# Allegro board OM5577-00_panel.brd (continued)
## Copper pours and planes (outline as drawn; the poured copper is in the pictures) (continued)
(no net) on TOP, IS1, IS2: 286,5.5 272.7,5.5 272.7,8.65 271.85,9.5 246.55,9.5 245.7,8.65 245.7,0.5 232.5,0.5 232.5,68.5 232.51,68.5 234.25,68.5 234.25,29.45 284.25,29.45 284.25,68.5 285.99,68.5 286,68.5
(no net) on TOP, IS1, IS2: 54,5.5 40.7,5.5 40.7,8.65 39.85,9.5 14.55,9.5 13.7,8.65 13.7,0.5 0.5,0.5 0.5,68.5 0.51,68.5 2.25,68.5 2.25,29.45 52.25,29.45 52.25,68.5 53.99,68.5 54,68.5
(no net) on TOP, IS1, IS2: 228,5.5 214.7,5.5 214.7,8.65 213.85,9.5 188.55,9.5 187.7,8.65 187.7,0.5 174.5,0.5 174.5,68.5 174.51,68.5 176.25,68.5 176.25,29.45 226.25,29.45 226.25,68.5 227.99,68.5 228,68.5
(no net) on TOP, IS1, IS2: 170,5.5 156.7,5.5 156.7,8.65 155.85,9.5 130.55,9.5 129.7,8.65 129.7,0.5 116.5,0.5 116.5,68.5 116.51,68.5 118.25,68.5 118.25,29.45 168.25,29.45 168.25,68.5 169.99,68.5 170,68.5
(no net) on BOTTOM: 187.5,169.5 147.5,169.5 147.5,193 166.7,193 166.7,194.25 167.15,194.7 167.75,194.7 168.2,194.25 168.2,193 187.5,193 ; 3 cut-outs
(no net) on BOTTOM: 104.75,22.38 101.67,19.3 101.69,19.26 101.77,18.96 101.78,18.66 101.86,18.51 102.03,18.54 105.15,21.66 105.15,29.16 105.44,29.45 105.95,29.45 105.95,29.96 106.49,30.5 107.12,30.5 107.18,30.54 107.18,30.62 107.15,30.66 107.13,30.7 106.21,30.7 110.25,34.74 110.25,68.5 111.99,68.5 112,68.5 112,5.5 98.7,5.5 98.7,8.65 97.85,9.5 72.55,9.5 71.7,8.65 71.7,0.5 58.5,0.5 58.5,68.5 58.51,68.5 60.25,68.5 60.25,29.45 104.96,29.45 104.75,29.24
(no net) on BOTTOM: 234.75,169.5 194.75,169.5 194.75,193 213.95,193 213.95,194.25 214.4,194.7 215,194.7 215.45,194.25 215.45,193 234.75,193 ; 3 cut-outs
(no net) on BOTTOM: 113.5,80.05 110.94,77.5 61.01,77.5 58.5,80 58.5,159 61,161.5 110.95,161.5 113.5,158.95 ; 7 cut-outs
(no net) on BOTTOM: 45.75,169.5 5.75,169.5 5.75,193 24.95,193 24.95,194.25 25.4,194.7 26,194.7 26.45,194.25 26.45,193 45.75,193 ; 3 cut-outs
(no net) on BOTTOM: 140.25,169.5 100.25,169.5 100.25,193 119.45,193 119.45,194.25 119.9,194.7 120.5,194.7 120.95,194.25 120.95,193 140.25,193 ; 3 cut-outs
(no net) on BOTTOM: 93,169.5 53,169.5 53,193 72.2,193 72.2,194.25 72.65,194.7 73.25,194.7 73.7,194.25 73.7,193 93,193 ; 3 cut-outs
(no net) on BOTTOM: 278.75,22.38 275.67,19.3 275.69,19.26 275.77,18.96 275.78,18.66 275.86,18.51 276.03,18.54 279.15,21.66 279.15,29.16 279.44,29.45 279.95,29.45 279.95,29.96 280.49,30.5 281.12,30.5 281.18,30.54 281.18,30.62 281.15,30.66 281.13,30.7 280.21,30.7 284.25,34.74 284.25,68.5 285.99,68.5 286,68.5 286,5.5 272.7,5.5 272.7,8.65 271.85,9.5 246.55,9.5 245.7,8.65 245.7,0.5 232.5,0.5 232.5,68.5 232.51,68.5 234.25,68.5 234.25,29.45 278.96,29.45 278.75,29.24
(no net) on BOTTOM: 220.75,22.38 217.67,19.3 217.69,19.26 217.77,18.96 217.78,18.66 217.86,18.51 218.03,18.54 221.15,21.66 221.15,29.16 221.44,29.45 221.95,29.45 221.95,29.96 222.49,30.5 223.12,30.5 223.18,30.54 223.18,30.62 223.15,30.66 223.13,30.7 222.21,30.7 226.25,34.74 226.25,68.5 227.99,68.5 228,68.5 228,5.5 214.7,5.5 214.7,8.65 213.85,9.5 188.55,9.5 187.7,8.65 187.7,0.5 174.5,0.5 174.5,68.5 174.51,68.5 176.25,68.5 176.25,29.45 220.96,29.45 220.75,29.24
(no net) on BOTTOM: 55.5,80.05 52.94,77.5 3.01,77.5 0.5,80 0.5,159 3,161.5 52.95,161.5 55.5,158.95 ; 7 cut-outs
(no net) on BOTTOM: 171.5,80.05 168.94,77.5 119.01,77.5 116.5,80 116.5,159 119,161.5 168.95,161.5 171.5,158.95 ; 7 cut-outs
(no net) on BOTTOM: 162.75,22.38 159.67,19.3 159.69,19.26 159.77,18.96 159.78,18.66 159.86,18.51 160.03,18.54 163.15,21.66 163.15,29.16 163.44,29.45 163.95,29.45 163.95,29.96 164.49,30.5 165.12,30.5 165.18,30.54 165.18,30.62 165.15,30.66 165.13,30.7 164.21,30.7 168.25,34.74 168.25,68.5 169.99,68.5 170,68.5 170,5.5 156.7,5.5 156.7,8.65 155.85,9.5 130.55,9.5 129.7,8.65 129.7,0.5 116.5,0.5 116.5,68.5 116.51,68.5 118.25,68.5 118.25,29.45 162.96,29.45 162.75,29.24
(no net) on BOTTOM: 46.75,22.38 43.67,19.3 43.69,19.26 43.77,18.96 43.78,18.66 43.86,18.51 44.03,18.54 47.15,21.66 47.15,29.16 47.44,29.45 47.95,29.45 47.95,29.96 48.49,30.5 49.12,30.5 49.18,30.54 49.18,30.62 49.15,30.66 49.13,30.7 48.21,30.7 52.25,34.74 52.25,68.5 53.99,68.5 54,68.5 54,5.5 40.7,5.5 40.7,8.65 39.85,9.5 14.55,9.5 13.7,8.65 13.7,0.5 0.5,0.5 0.5,68.5 0.51,68.5 2.25,68.5 2.25,29.45 46.96,29.45 46.75,29.24
(no net) on BOTTOM: 282,169.5 242,169.5 242,193 261.2,193 261.2,194.25 261.65,194.7 262.25,194.7 262.7,194.25 262.7,193 282,193 ; 3 cut-outs
(no net) on BOTTOM: 229.5,80.05 226.94,77.5 177.01,77.5 174.5,80 174.5,159 177,161.5 226.95,161.5 229.5,158.95 ; 7 cut-outs
(no net) on BOTTOM: 287.5,80.05 284.94,77.5 235.01,77.5 232.5,80 232.5,159 235,161.5 284.95,161.5 287.5,158.95 ; 7 cut-outs
(no net) on IS1, IS2: 45.75,169.5 5.75,169.5 5.75,193 24.95,193 24.95,194.25 25.4,194.7 26,194.7 26.45,194.25 26.45,193 45.75,193
(no net) on IS1, IS2: 234.75,169.5 194.75,169.5 194.75,193 213.95,193 213.95,194.25 214.4,194.7 215,194.7 215.45,194.25 215.45,193 234.75,193
(no net) on IS1, IS2: 282,169.5 242,169.5 242,193 261.2,193 261.2,194.25 261.65,194.7 262.25,194.7 262.7,194.25 262.7,193 282,193
(no net) on IS1, IS2: 93,169.5 53,169.5 53,193 72.2,193 72.2,194.25 72.65,194.7 73.25,194.7 73.7,194.25 73.7,193 93,193
(no net) on IS1, IS2: 140.25,169.5 100.25,169.5 100.25,193 119.45,193 119.45,194.25 119.9,194.7 120.5,194.7 120.95,194.25 120.95,193 140.25,193
(no net) on IS1, IS2: 187.5,169.5 147.5,169.5 147.5,193 166.7,193 166.7,194.25 167.15,194.7 167.75,194.7 168.2,194.25 168.2,193 187.5,193
(no net) on IS2: 287.5,80.05 284.94,77.5 235.01,77.5 232.5,80 232.5,159 235,161.5 284.95,161.5 287.5,158.95 ; 1 cut-out
(no net) on IS2: 113.5,80.05 110.94,77.5 61.01,77.5 58.5,80 58.5,159 61,161.5 110.95,161.5 113.5,158.95 ; 1 cut-out
(no net) on IS2: 229.5,80.05 226.94,77.5 177.01,77.5 174.5,80 174.5,159 177,161.5 226.95,161.5 229.5,158.95 ; 1 cut-out
(no net) on IS2: 171.5,80.05 168.94,77.5 119.01,77.5 116.5,80 116.5,159 119,161.5 168.95,161.5 171.5,158.95 ; 1 cut-out
(no net) on IS2: 55.5,80.05 52.94,77.5 3.01,77.5 0.5,80 0.5,159 3,161.5 52.95,161.5 55.5,158.95 ; 1 cut-out
A_1_GND on TOP (solid shape): 30.85,187.11 28.83,187.11 28.83,188.44 30.85,188.44
A_1_GND on TOP (solid shape): 22.59,187.11 20.55,187.11 20.55,188.44 22.59,188.44
A_1_GND on TOP (solid shape): 25.89,183.87 27.17,183.87 27.17,182.41 24.26,182.41 24.26,182.46 24.21,182.46 24.21,183.87 25.51,183.87 25.51,186.99 25.89,186.99
A_1_GND on TOP (solid shape): 26.45,194.25 26.45,193 26.76,193 26.91,192.9 26.86,192.73 26.51,191.56 27.5,190.85 28.5,190.85 29.5,191.56 29.09,192.9 29.24,193 29.79,193 30.2,191.68 30.43,190.32 30.4,190.21 30.28,190.16 27.17,190.16 27.17,190.11 24.26,190.11 24.26,190.16 21.12,190.16 21,190.21 20.97,190.32 21.2,191.68 21.61,193 24.95,193 24.95,194.25 25.4,194.7 26,194.7
A_1_GND on TOP (solid shape): outline of 1396 points within 5.75,169.5 45.75,193
A_1_GND on BOTTOM (solid shape): outline of 1591 points within 5.75,169.5 45.75,194.7
A_1_GND on IS1 (solid shape): outline of 2475 points within 5.75,169.5 45.75,194.7
A_1_GND on IS2 (solid shape): 39.8,178.35 40.08,177.9 40.52,177.62 40.62,177.48 40.52,177.34 40.06,177.04 39.78,176.56 39.77,176.54 39.01,175.78 38.84,175.74 38.75,175.88 38.39,176.69 37.54,176.94 37.39,177.02 37.41,177.19 38.57,178.35
A_1_GND on IS2 (solid shape): 8.79,177.47 8.9,177.43 9.2,177.13 9.2,175.88 12.13,172.95 31.62,172.95 32.26,173.59 32.28,173.59 32.41,173.63 32.52,173.7 38.07,173.7 39.8,175.43 39.91,175.48 40.02,175.42 40.18,175.27 40.36,175.15 40.43,174.99 40.28,174.87 39.73,174.87 39.73,173.3 33.67,173.3 33.16,173.38 32.84,172.98 32.84,172.96 31.93,172.05 20.37,172.05 20.05,172.16 19.73,172.05 12.02,172.05 9,175.07 9,176.9 8.45,176.9 8.3,177.02 8.37,177.18 8.54,177.29 8.69,177.43
A_1_GND on IS2 (solid shape): 15.83,176.55 21.63,176.55 22.08,176.1 28.2,176.1 28.3,176.09 28.4,176.1 30.63,176.1 31.18,175.55 33.67,175.55 39.01,180.89 39.8,180.89 40.08,180.44 40.52,180.16 40.62,180.02 40.52,179.88 40.08,179.6 39.8,179.15 38.23,179.15 34.38,175.3 31.17,175.3 30.67,175.8 28.62,175.8 28.42,175.9 28.21,175.9 28.2,175.9 21.78,175.9 21.53,175.65 15.27,175.65 9.74,181.18 8.93,181.18 8.65,181.63 8.21,181.91 8.11,182.05 8.21,182.19 8.65,182.47 8.93,182.92 9.46,182.92
A_1_GND on IS2 (solid shape): 16.58,178.05 22.03,178.05 22.68,177.4 29.62,177.4 30.27,178.05 31.07,178.05 31.19,177.99 31.21,177.85 31.8,177.2 32.09,178.03 32.06,178.13 32.1,178.23 32.21,178.34 32.23,178.34 32.36,178.38 32.47,178.45 34.42,178.45 39.4,183.43 39.8,183.43 40.08,182.98 40.52,182.7 40.62,182.56 40.52,182.42 40.08,182.14 39.8,181.69 38.67,181.69 33.33,176.35 31.52,176.35 30.97,176.9 28.71,176.9 28.3,177.11 27.89,176.9 22.42,176.9 21.97,177.35 16.17,177.35 9.8,183.72 8.93,183.72 8.65,184.17 8.21,184.45 8.11,184.59 8.21,184.73 8.65,185.01 8.93,185.46 9.17,185.46
A_1_GND on IS2 (solid shape): 14.93,174.85 21.87,174.85 22.12,175.1 23.09,175.1 23.21,175.03 23.23,174.89 23.7,174.19 24.18,174.89 24.19,175.03 24.31,175.1 24.67,175.1 24.8,175.01 24.78,174.85 25.18,174.01 25.57,174.85 25.55,175.01 25.68,175.1 27.89,175.1 28.23,174.89 28.62,175 30.33,175 30.7,174.63 30.74,174.53 30.71,174.43 30.6,174.2 30.61,173.95 30.59,173.81 30.47,173.75 12.47,173.75 10.69,175.53 10.66,175.71 10.83,175.78 12.05,177.25 10.14,177.24 10.12,177.2 10,177.2 10,177.47 8.97,178.49 8.97,178.51 8.7,179.04 8.21,179.37 8.11,179.51 8.21,179.65 8.65,179.93 8.93,180.38 9.4,180.38
A_1_GND on IS2 (solid shape): outline of 1337 points within 5.75,169.5 45.75,194.7
A_2_GND on TOP (solid shape): 78.1,187.11 76.08,187.11 76.08,188.44 78.1,188.44
A_2_GND on TOP (solid shape): 69.84,187.11 67.8,187.11 67.8,188.44 69.84,188.44
A_2_GND on TOP (solid shape): 73.14,183.87 74.42,183.87 74.42,182.41 71.51,182.41 71.51,182.46 71.46,182.46 71.46,183.87 72.76,183.87 72.76,186.99 73.14,186.99
A_2_GND on TOP (solid shape): 73.7,194.25 73.7,193 74.01,193 74.16,192.9 74.11,192.73 73.76,191.56 74.75,190.85 75.75,190.85 76.75,191.56 76.34,192.9 76.49,193 77.04,193 77.45,191.68 77.68,190.32 77.65,190.21 77.53,190.16 74.42,190.16 74.42,190.11 71.51,190.11 71.51,190.16 68.37,190.16 68.25,190.21 68.22,190.32 68.45,191.68 68.86,193 72.2,193 72.2,194.25 72.65,194.7 73.25,194.7
A_2_GND on TOP (solid shape): outline of 1395 points within 53,169.5 93,193
A_2_GND on BOTTOM (solid shape): outline of 1590 points within 53,169.5 93,194.7
A_2_GND on IS1 (solid shape): outline of 2474 points within 53,169.5 93,194.7
A_2_GND on IS2 (solid shape): 87.05,178.35 87.33,177.9 87.77,177.62 87.87,177.48 87.77,177.34 87.31,177.04 87.03,176.56 87.03,176.54 86.26,175.78 86.09,175.74 86,175.88 85.64,176.69 84.79,176.94 84.64,177.02 84.66,177.19 85.82,178.35
A_2_GND on IS2 (solid shape): 56.04,177.47 56.15,177.43 56.45,177.13 56.45,175.88 59.38,172.95 78.87,172.95 79.51,173.59 79.53,173.59 79.66,173.63 79.77,173.7 85.32,173.7 87.05,175.43 87.16,175.48 87.27,175.42 87.43,175.27 87.61,175.15 87.68,174.99 87.53,174.87 86.98,174.87 86.98,173.3 80.92,173.3 80.41,173.38 80.09,172.98 80.09,172.96 79.18,172.05 67.62,172.05 67.3,172.16 66.98,172.05 59.27,172.05 56.25,175.07 56.25,176.9 55.7,176.9 55.55,177.02 55.62,177.18 55.79,177.29 55.94,177.43
A_2_GND on IS2 (solid shape): 63.08,176.55 68.88,176.55 69.33,176.1 75.45,176.1 75.55,176.09 75.65,176.1 77.88,176.1 78.43,175.55 80.92,175.55 86.26,180.89 87.05,180.89 87.33,180.44 87.77,180.16 87.87,180.02 87.77,179.88 87.33,179.6 87.05,179.15 85.48,179.15 81.63,175.3 78.42,175.3 77.92,175.8 75.87,175.8 75.67,175.9 75.46,175.9 75.45,175.9 69.03,175.9 68.78,175.65 62.52,175.65 56.99,181.18 56.18,181.18 55.9,181.63 55.46,181.91 55.36,182.05 55.46,182.19 55.9,182.47 56.18,182.92 56.71,182.92
A_2_GND on IS2 (solid shape): 63.83,178.05 69.28,178.05 69.93,177.4 76.87,177.4 77.52,178.05 78.32,178.05 78.44,177.99 78.46,177.85 79.05,177.2 79.34,178.03 79.31,178.13 79.35,178.23 79.46,178.34 79.48,178.34 79.61,178.38 79.72,178.45 81.67,178.45 86.65,183.43 87.05,183.43 87.33,182.98 87.77,182.7 87.87,182.56 87.77,182.42 87.33,182.14 87.05,181.69 85.92,181.69 80.58,176.35 78.77,176.35 78.22,176.9 75.96,176.9 75.55,177.11 75.14,176.9 69.67,176.9 69.22,177.35 63.42,177.35 57.05,183.72 56.18,183.72 55.9,184.17 55.46,184.45 55.36,184.59 55.46,184.73 55.9,185.01 56.18,185.46 56.42,185.46
A_2_GND on IS2 (solid shape): 62.18,174.85 69.12,174.85 69.37,175.1 70.34,175.1 70.46,175.03 70.47,174.89 70.95,174.19 71.42,174.89 71.44,175.03 71.56,175.1 71.92,175.1 72.05,175.01 72.03,174.85 72.42,174.01 72.82,174.85 72.8,175.01 72.93,175.1 75.14,175.1 75.48,174.89 75.87,175 77.58,175 77.95,174.63 77.99,174.53 77.96,174.43 77.85,174.2 77.86,173.95 77.84,173.81 77.72,173.75 59.72,173.75 57.94,175.53 57.91,175.71 58.08,175.78 59.3,177.25 57.4,177.24 57.38,177.2 57.25,177.2 57.25,177.47 56.23,178.49 56.22,178.51 55.95,179.04 55.46,179.37 55.36,179.51 55.46,179.65 55.9,179.93 56.18,180.38 56.65,180.38
A_2_GND on IS2 (solid shape): outline of 1337 points within 53,169.5 93,194.7
A_3_GND on TOP (solid shape): 125.35,187.11 123.33,187.11 123.33,188.44 125.35,188.44
A_3_GND on TOP (solid shape): 117.09,187.11 115.05,187.11 115.05,188.44 117.09,188.44
A_3_GND on TOP (solid shape): 120.39,183.87 121.67,183.87 121.67,182.41 118.76,182.41 118.76,182.46 118.71,182.46 118.71,183.87 120.01,183.87 120.01,186.99 120.39,186.99
A_3_GND on TOP (solid shape): 120.95,194.25 120.95,193 121.26,193 121.41,192.9 121.36,192.73 121.01,191.56 122,190.85 123,190.85 124,191.56 123.59,192.9 123.74,193 124.29,193 124.7,191.68 124.93,190.32 124.9,190.21 124.78,190.16 121.67,190.16 121.67,190.11 118.76,190.11 118.76,190.16 115.62,190.16 115.5,190.21 115.47,190.32 115.7,191.68 116.11,193 119.45,193 119.45,194.25 119.9,194.7 120.5,194.7
A_3_GND on TOP (solid shape): outline of 1395 points within 100.25,169.5 140.25,193
A_3_GND on BOTTOM (solid shape): outline of 1590 points within 100.25,169.5 140.25,194.7
A_3_GND on IS1 (solid shape): outline of 2474 points within 100.25,169.5 140.25,194.7
A_3_GND on IS2 (solid shape): 134.3,178.35 134.58,177.9 135.02,177.62 135.12,177.48 135.02,177.34 134.56,177.04 134.28,176.56 134.28,176.54 133.51,175.78 133.34,175.74 133.25,175.88 132.89,176.69 132.04,176.94 131.89,177.02 131.91,177.19 133.07,178.35
A_3_GND on IS2 (solid shape): 103.29,177.47 103.4,177.43 103.7,177.13 103.7,175.88 106.63,172.95 126.12,172.95 126.76,173.59 126.78,173.59 126.91,173.63 127.02,173.7 132.57,173.7 134.3,175.43 134.41,175.48 134.52,175.42 134.68,175.27 134.86,175.15 134.93,174.99 134.78,174.87 134.23,174.87 134.23,173.3 128.17,173.3 127.66,173.38 127.34,172.98 127.34,172.96 126.43,172.05 114.87,172.05 114.55,172.16 114.23,172.05 106.52,172.05 103.5,175.07 103.5,176.9 102.94,176.9 102.8,177.02 102.87,177.18 103.04,177.29 103.19,177.43
A_3_GND on IS2 (solid shape): 110.33,176.55 116.13,176.55 116.58,176.1 122.7,176.1 122.8,176.09 122.9,176.1 125.13,176.1 125.68,175.55 128.17,175.55 133.51,180.89 134.3,180.89 134.58,180.44 135.02,180.16 135.12,180.02 135.02,179.88 134.58,179.6 134.3,179.15 132.73,179.15 128.88,175.3 125.67,175.3 125.17,175.8 123.12,175.8 122.92,175.9 122.71,175.9 122.7,175.9 116.28,175.9 116.03,175.65 109.77,175.65 104.24,181.18 103.43,181.18 103.15,181.63 102.71,181.91 102.61,182.05 102.71,182.19 103.15,182.47 103.43,182.92 103.96,182.92
A_3_GND on IS2 (solid shape): 111.08,178.05 116.53,178.05 117.18,177.4 124.12,177.4 124.77,178.05 125.57,178.05 125.69,177.99 125.71,177.85 126.3,177.2 126.59,178.03 126.56,178.13 126.6,178.23 126.71,178.34 126.73,178.34 126.86,178.38 126.97,178.45 128.92,178.45 133.9,183.43 134.3,183.43 134.58,182.98 135.02,182.7 135.12,182.56 135.02,182.42 134.58,182.14 134.3,181.69 133.17,181.69 127.83,176.35 126.02,176.35 125.47,176.9 123.21,176.9 122.8,177.11 122.39,176.9 116.92,176.9 116.47,177.35 110.67,177.35 104.3,183.72 103.43,183.72 103.15,184.17 102.71,184.45 102.61,184.59 102.71,184.73 103.15,185.01 103.43,185.46 103.67,185.46
A_3_GND on IS2 (solid shape): 109.43,174.85 116.37,174.85 116.62,175.1 117.59,175.1 117.71,175.03 117.72,174.89 118.2,174.19 118.67,174.89 118.69,175.03 118.81,175.1 119.17,175.1 119.3,175.01 119.28,174.85 119.67,174.01 120.07,174.85 120.05,175.01 120.18,175.1 122.39,175.1 122.73,174.89 123.12,175 124.83,175 125.2,174.63 125.24,174.53 125.21,174.43 125.1,174.2 125.11,173.95 125.09,173.81 124.97,173.75 106.97,173.75 105.19,175.53 105.16,175.71 105.33,175.78 106.55,177.25 104.64,177.24 104.62,177.2 104.5,177.2 104.5,177.47 103.47,178.49 103.47,178.51 103.2,179.04 102.71,179.37 102.61,179.51 102.71,179.65 103.15,179.93 103.43,180.38 103.9,180.38
A_3_GND on IS2 (solid shape): outline of 1337 points within 100.25,169.5 140.25,194.7
A_4_GND on TOP (solid shape): 172.6,187.11 170.58,187.11 170.58,188.44 172.6,188.44
A_4_GND on TOP (solid shape): 164.34,187.11 162.3,187.11 162.3,188.44 164.34,188.44
A_4_GND on TOP (solid shape): 167.64,183.87 168.92,183.87 168.92,182.41 166.01,182.41 166.01,182.46 165.96,182.46 165.96,183.87 167.26,183.87 167.26,186.99 167.64,186.99
A_4_GND on TOP (solid shape): 168.2,194.25 168.2,193 168.51,193 168.66,192.9 168.61,192.73 168.26,191.56 169.25,190.85 170.25,190.85 171.25,191.56 170.84,192.9 170.99,193 171.54,193 171.95,191.68 172.18,190.32 172.15,190.21 172.03,190.16 168.92,190.16 168.92,190.11 166.01,190.11 166.01,190.16 162.87,190.16 162.75,190.21 162.72,190.32 162.95,191.68 163.36,193 166.7,193 166.7,194.25 167.15,194.7 167.75,194.7
A_4_GND on TOP (solid shape): outline of 1395 points within 147.5,169.5 187.5,193
A_4_GND on BOTTOM (solid shape): outline of 1590 points within 147.5,169.5 187.5,194.7
A_4_GND on IS1 (solid shape): outline of 2476 points within 147.5,169.5 187.5,194.7
A_4_GND on IS2 (solid shape): 181.55,178.35 181.83,177.9 182.27,177.62 182.37,177.48 182.27,177.34 181.81,177.04 181.53,176.56 181.53,176.54 180.76,175.78 180.59,175.74 180.5,175.88 180.14,176.69 179.29,176.94 179.14,177.02 179.16,177.19 180.32,178.35
A_4_GND on IS2 (solid shape): 150.54,177.47 150.65,177.43 150.95,177.13 150.95,175.88 153.88,172.95 173.37,172.95 174.01,173.59 174.03,173.59 174.16,173.63 174.27,173.7 179.82,173.7 181.55,175.43 181.66,175.48 181.77,175.42 181.93,175.27 182.11,175.15 182.18,174.99 182.03,174.87 181.48,174.87 181.48,173.3 175.42,173.3 174.91,173.38 174.59,172.98 174.59,172.96 173.68,172.05 162.12,172.05 161.8,172.16 161.48,172.05 153.77,172.05 150.75,175.07 150.75,176.9 150.19,176.9 150.05,177.02 150.12,177.18 150.29,177.29 150.44,177.43
A_4_GND on IS2 (solid shape): 157.58,176.55 163.38,176.55 163.83,176.1 169.95,176.1 170.05,176.09 170.15,176.1 172.38,176.1 172.93,175.55 175.42,175.55 180.76,180.89 181.55,180.89 181.83,180.44 182.27,180.16 182.37,180.02 182.27,179.88 181.83,179.6 181.55,179.15 179.98,179.15 176.13,175.3 172.92,175.3 172.42,175.8 170.37,175.8 170.17,175.9 169.96,175.9 169.95,175.9 163.53,175.9 163.28,175.65 157.02,175.65 151.49,181.18 150.68,181.18 150.4,181.63 149.96,181.91 149.86,182.05 149.96,182.19 150.4,182.47 150.68,182.92 151.21,182.92
A_4_GND on IS2 (solid shape): 158.33,178.05 163.78,178.05 164.43,177.4 171.37,177.4 172.02,178.05 172.82,178.05 172.94,177.99 172.96,177.85 173.55,177.2 173.84,178.03 173.81,178.13 173.85,178.23 173.96,178.34 173.98,178.34 174.11,178.38 174.22,178.45 176.17,178.45 181.15,183.43 181.55,183.43 181.83,182.98 182.27,182.7 182.37,182.56 182.27,182.42 181.83,182.14 181.55,181.69 180.42,181.69 175.08,176.35 173.27,176.35 172.72,176.9 170.46,176.9 170.05,177.11 169.64,176.9 164.17,176.9 163.72,177.35 157.92,177.35 151.55,183.72 150.68,183.72 150.4,184.17 149.96,184.45 149.86,184.59 149.96,184.73 150.4,185.01 150.68,185.46 150.92,185.46
A_4_GND on IS2 (solid shape): 156.68,174.85 163.62,174.85 163.87,175.1 164.84,175.1 164.96,175.03 164.97,174.89 165.45,174.19 165.93,174.89 165.94,175.03 166.06,175.1 166.42,175.1 166.55,175.01 166.53,174.85 166.93,174.01 167.32,174.85 167.3,175.01 167.43,175.1 169.64,175.1 169.98,174.89 170.37,175 172.08,175 172.45,174.63 172.49,174.53 172.46,174.43 172.35,174.2 172.36,173.95 172.34,173.81 172.22,173.75 154.22,173.75 152.44,175.53 152.41,175.71 152.58,175.78 153.8,177.25 151.9,177.24 151.88,177.2 151.75,177.2 151.75,177.47 150.72,178.49 150.72,178.51 150.45,179.04 149.96,179.37 149.86,179.51 149.96,179.65 150.4,179.93 150.68,180.38 151.15,180.38
A_4_GND on IS2 (solid shape): outline of 1337 points within 147.5,169.5 187.5,194.7
A_5_GND on TOP (solid shape): 219.85,187.11 217.83,187.11 217.83,188.44 219.85,188.44
A_5_GND on TOP (solid shape): 211.59,187.11 209.55,187.11 209.55,188.44 211.59,188.44
A_5_GND on TOP (solid shape): 214.89,183.87 216.17,183.87 216.17,182.41 213.26,182.41 213.26,182.46 213.21,182.46 213.21,183.87 214.51,183.87 214.51,186.99 214.89,186.99
A_5_GND on TOP (solid shape): 215.45,194.25 215.45,193 215.76,193 215.91,192.9 215.86,192.73 215.51,191.56 216.5,190.85 217.5,190.85 218.5,191.56 218.09,192.9 218.24,193 218.79,193 219.2,191.68 219.43,190.32 219.4,190.21 219.28,190.16 216.17,190.16 216.17,190.11 213.26,190.11 213.26,190.16 210.12,190.16 210,190.21 209.97,190.32 210.2,191.68 210.61,193 213.95,193 213.95,194.25 214.4,194.7 215,194.7
A_5_GND on TOP (solid shape): outline of 1395 points within 194.75,169.5 234.75,193
A_5_GND on BOTTOM (solid shape): outline of 1590 points within 194.75,169.5 234.75,194.7
A_5_GND on IS1 (solid shape): outline of 2476 points within 194.75,169.5 234.75,194.7
A_5_GND on IS2 (solid shape): 228.8,178.35 229.08,177.9 229.52,177.62 229.62,177.48 229.52,177.34 229.06,177.04 228.78,176.56 228.78,176.54 228.01,175.78 227.84,175.74 227.75,175.88 227.39,176.69 226.54,176.94 226.39,177.02 226.41,177.19 227.57,178.35
A_5_GND on IS2 (solid shape): 197.79,177.47 197.9,177.43 198.2,177.13 198.2,175.88 201.13,172.95 220.62,172.95 221.26,173.59 221.28,173.59 221.41,173.63 221.52,173.7 227.07,173.7 228.8,175.43 228.91,175.48 229.02,175.42 229.18,175.27 229.36,175.15 229.43,174.99 229.28,174.87 228.73,174.87 228.73,173.3 222.67,173.3 222.16,173.38 221.84,172.98 221.84,172.96 220.93,172.05 209.37,172.05 209.05,172.16 208.73,172.05 201.02,172.05 198,175.07 198,176.9 197.44,176.9 197.3,177.02 197.37,177.18 197.54,177.29 197.69,177.43
A_5_GND on IS2 (solid shape): 204.83,176.55 210.63,176.55 211.08,176.1 217.2,176.1 217.3,176.09 217.4,176.1 219.63,176.1 220.18,175.55 222.67,175.55 228.01,180.89 228.8,180.89 229.08,180.44 229.52,180.16 229.62,180.02 229.52,179.88 229.08,179.6 228.8,179.15 227.23,179.15 223.38,175.3 220.17,175.3 219.67,175.8 217.62,175.8 217.42,175.9 217.21,175.9 217.2,175.9 210.78,175.9 210.53,175.65 204.27,175.65 198.74,181.18 197.93,181.18 197.65,181.63 197.21,181.91 197.11,182.05 197.21,182.19 197.65,182.47 197.93,182.92 198.46,182.92
A_5_GND on IS2 (solid shape): 205.58,178.05 211.03,178.05 211.68,177.4 218.62,177.4 219.27,178.05 220.07,178.05 220.19,177.99 220.21,177.85 220.8,177.2 221.09,178.03 221.06,178.13 221.1,178.23 221.21,178.34 221.23,178.34 221.36,178.38 221.47,178.45 223.42,178.45 228.4,183.43 228.8,183.43 229.08,182.98 229.52,182.7 229.62,182.56 229.52,182.42 229.08,182.14 228.8,181.69 227.67,181.69 222.33,176.35 220.52,176.35 219.97,176.9 217.71,176.9 217.3,177.11 216.89,176.9 211.42,176.9 210.97,177.35 205.17,177.35 198.8,183.72 197.93,183.72 197.65,184.17 197.21,184.45 197.11,184.59 197.21,184.73 197.65,185.01 197.93,185.46 198.17,185.46
A_5_GND on IS2 (solid shape): 203.93,174.85 210.87,174.85 211.12,175.1 212.09,175.1 212.21,175.03 212.22,174.89 212.7,174.19 213.18,174.89 213.19,175.03 213.31,175.1 213.67,175.1 213.8,175.01 213.78,174.85 214.18,174.01 214.57,174.85 214.55,175.01 214.68,175.1 216.89,175.1 217.23,174.89 217.62,175 219.33,175 219.7,174.63 219.74,174.53 219.71,174.43 219.6,174.2 219.61,173.95 219.59,173.81 219.47,173.75 201.47,173.75 199.69,175.53 199.66,175.71 199.83,175.78 201.05,177.25 199.15,177.24 199.12,177.2 199,177.2 199,177.47 197.97,178.49 197.97,178.51 197.7,179.04 197.21,179.37 197.11,179.51 197.21,179.65 197.65,179.93 197.93,180.38 198.4,180.38
A_5_GND on IS2 (solid shape): outline of 1337 points within 194.75,169.5 234.75,194.7
A_6_GND on TOP (solid shape): 267.1,187.11 265.08,187.11 265.08,188.44 267.1,188.44
A_6_GND on TOP (solid shape): 258.84,187.11 256.8,187.11 256.8,188.44 258.84,188.44
A_6_GND on TOP (solid shape): 262.14,183.87 263.42,183.87 263.42,182.41 260.51,182.41 260.51,182.46 260.46,182.46 260.46,183.87 261.76,183.87 261.76,186.99 262.14,186.99
A_6_GND on TOP (solid shape): 262.7,194.25 262.7,193 263.01,193 263.16,192.9 263.11,192.73 262.76,191.56 263.75,190.85 264.75,190.85 265.75,191.56 265.34,192.9 265.49,193 266.04,193 266.45,191.68 266.68,190.32 266.65,190.21 266.53,190.16 263.42,190.16 263.42,190.11 260.51,190.11 260.51,190.16 257.37,190.16 257.25,190.21 257.22,190.32 257.45,191.68 257.86,193 261.2,193 261.2,194.25 261.65,194.7 262.25,194.7
A_6_GND on TOP (solid shape): outline of 1395 points within 242,169.5 282,193
A_6_GND on BOTTOM (solid shape): outline of 1590 points within 242,169.5 282,194.7
A_6_GND on IS1 (solid shape): outline of 2474 points within 242,169.5 282,194.7
A_6_GND on IS2 (solid shape): 276.05,178.35 276.33,177.9 276.77,177.62 276.87,177.48 276.77,177.34 276.31,177.04 276.03,176.56 276.02,176.54 275.26,175.78 275.09,175.74 275,175.88 274.64,176.69 273.79,176.94 273.64,177.02 273.66,177.19 274.82,178.35
A_6_GND on IS2 (solid shape): 245.04,177.47 245.15,177.43 245.45,177.13 245.45,175.88 248.38,172.95 267.87,172.95 268.51,173.59 268.53,173.59 268.66,173.63 268.77,173.7 274.32,173.7 276.05,175.43 276.16,175.48 276.27,175.42 276.43,175.27 276.61,175.15 276.68,174.99 276.54,174.87 275.98,174.87 275.98,173.3 269.92,173.3 269.41,173.38 269.1,172.98 269.09,172.96 268.18,172.05 256.62,172.05 256.3,172.16 255.98,172.05 248.27,172.05 245.25,175.07 245.25,176.9 244.69,176.9 244.55,177.02 244.62,177.18 244.79,177.29 244.94,177.43
A_6_GND on IS2 (solid shape): 252.08,176.55 257.88,176.55 258.33,176.1 264.45,176.1 264.55,176.09 264.65,176.1 266.88,176.1 267.43,175.55 269.92,175.55 275.26,180.89 276.05,180.89 276.33,180.44 276.77,180.16 276.87,180.02 276.77,179.88 276.33,179.6 276.05,179.15 274.48,179.15 270.63,175.3 267.42,175.3 266.92,175.8 264.87,175.8 264.67,175.9 264.46,175.9 264.45,175.9 258.03,175.9 257.78,175.65 251.52,175.65 245.99,181.18 245.18,181.18 244.9,181.63 244.46,181.91 244.36,182.05 244.46,182.19 244.9,182.47 245.18,182.92 245.71,182.92
A_6_GND on IS2 (solid shape): 252.83,178.05 258.28,178.05 258.93,177.4 265.87,177.4 266.52,178.05 267.32,178.05 267.44,177.99 267.46,177.85 268.05,177.2 268.34,178.03 268.31,178.13 268.35,178.23 268.46,178.34 268.48,178.34 268.61,178.38 268.72,178.45 270.67,178.45 275.65,183.43 276.05,183.43 276.33,182.98 276.77,182.7 276.87,182.56 276.77,182.42 276.33,182.14 276.05,181.69 274.92,181.69 269.58,176.35 267.77,176.35 267.22,176.9 264.96,176.9 264.55,177.11 264.14,176.9 258.67,176.9 258.22,177.35 252.42,177.35 246.05,183.72 245.18,183.72 244.9,184.17 244.46,184.45 244.36,184.59 244.46,184.73 244.9,185.01 245.18,185.46 245.42,185.46
A_6_GND on IS2 (solid shape): 251.18,174.85 258.12,174.85 258.37,175.1 259.34,175.1 259.46,175.03 259.48,174.89 259.95,174.19 260.43,174.89 260.44,175.03 260.56,175.1 260.92,175.1 261.05,175.01 261.03,174.85 261.43,174.01 261.82,174.85 261.8,175.01 261.93,175.1 264.14,175.1 264.48,174.89 264.87,175 266.58,175 266.95,174.63 266.99,174.53 266.96,174.43 266.85,174.2 266.86,173.95 266.84,173.81 266.72,173.75 248.72,173.75 246.94,175.53 246.91,175.71 247.08,175.78 248.3,177.25 246.4,177.24 246.38,177.2 246.25,177.2 246.25,177.47 245.22,178.49 245.22,178.51 244.95,179.04 244.46,179.37 244.36,179.51 244.46,179.65 244.9,179.93 245.18,180.38 245.65,180.38
A_6_GND on IS2 (solid shape): outline of 1337 points within 242,169.5 282,194.7
B_1_GND_2272419 on TOP (solid shape): outline of 5024 points within 0.5,0.5 54,68.5
B_1_GND_2272419 on BOTTOM (solid shape): outline of 4787 points within 0.5,0.5 54,68.5
B_1_GND_2272419 on IS1 (solid shape): outline of 4939 points within 0.5,0.5 54,68.5
B_1_GND_2272419 on IS2 (solid shape): outline of 4941 points within 0.5,0.5 54,68.5
B_2_GND_2272419 on TOP (solid shape): outline of 5024 points within 58.5,0.5 112,68.5
B_2_GND_2272419 on BOTTOM (solid shape): outline of 4787 points within 58.5,0.5 112,68.5
B_2_GND_2272419 on IS1 (solid shape): outline of 4939 points within 58.5,0.5 112,68.5
B_2_GND_2272419 on IS2 (solid shape): outline of 4941 points within 58.5,0.5 112,68.5
B_3_GND_2272419 on TOP (solid shape): outline of 5024 points within 116.5,0.5 170,68.5
B_3_GND_2272419 on BOTTOM (solid shape): outline of 4787 points within 116.5,0.5 170,68.5
B_3_GND_2272419 on IS1 (solid shape): outline of 4939 points within 116.5,0.5 170,68.5
B_3_GND_2272419 on IS2 (solid shape): outline of 4943 points within 116.5,0.5 170,68.5
B_4_GND_2272419 on TOP (solid shape): outline of 5024 points within 174.5,0.5 228,68.5
B_4_GND_2272419 on BOTTOM (solid shape): outline of 4787 points within 174.5,0.5 228,68.5
B_4_GND_2272419 on IS1 (solid shape): outline of 4939 points within 174.5,0.5 228,68.5
B_4_GND_2272419 on IS2 (solid shape): outline of 4943 points within 174.5,0.5 228,68.5
B_5_GND_2272419 on TOP (solid shape): outline of 5024 points within 232.5,0.5 286,68.5
B_5_GND_2272419 on BOTTOM (solid shape): outline of 4787 points within 232.5,0.5 286,68.5
B_5_GND_2272419 on IS1 (solid shape): outline of 4939 points within 232.5,0.5 286,68.5
B_5_GND_2272419 on IS2 (solid shape): outline of 4942 points within 232.5,0.5 286,68.5
C_1_GND_2270869 on TOP (solid shape): outline of 2297 points within 0.5,77.5 55.5,161.5
C_1_GND_2270869 on BOTTOM (solid shape): 11.95,96.45 11.95,85.75 10.81,84.61 10.64,84.58 10.55,84.72 10.55,85.05 10.29,85.05 10.15,85.14 10.18,85.31 10.54,86.4 9.92,87.38 9.85,87.51 9.92,87.64 10.55,88.78 9.92,89.92 9.85,90.05 9.92,90.18 10.55,91.32 9.92,92.46 9.85,92.59 9.92,92.72 10.55,93.89 9.88,95.03 9.8,95.16 9.88,95.29 10.49,96.2 10.18,97.25 10.16,97.41 10.3,97.5 10.9,97.5
C_1_GND_2270869 on BOTTOM (solid shape): outline of 1449 points within 0.5,77.5 55.5,161.5
C_1_GND_2270869 on IS1 (solid shape): outline of 2343 points within 0.5,77.5 55.5,161.5
C_1_GND_2270869 on IS2 (solid shape): outline of 2415 points within 0.5,77.5 55.5,161.5
C_2_GND_2270869 on TOP (solid shape): outline of 2370 points within 58.5,77.5 113.5,161.5
C_2_GND_2270869 on BOTTOM (solid shape): 69.95,96.45 69.95,85.75 68.81,84.61 68.64,84.58 68.55,84.72 68.55,85.05 68.29,85.05 68.15,85.14 68.18,85.31 68.54,86.4 67.92,87.38 67.85,87.51 67.92,87.64 68.55,88.78 67.92,89.92 67.85,90.05 67.92,90.18 68.55,91.32 67.92,92.46 67.85,92.59 67.92,92.72 68.55,93.89 67.88,95.03 67.8,95.16 67.88,95.29 68.49,96.2 68.19,97.25 68.16,97.41 68.3,97.5 68.9,97.5
C_2_GND_2270869 on BOTTOM (solid shape): outline of 1453 points within 58.5,77.5 113.5,161.5
C_2_GND_2270869 on IS1 (solid shape): outline of 2343 points within 58.5,77.5 113.5,161.5
C_2_GND_2270869 on IS2 (solid shape): outline of 2415 points within 58.5,77.5 113.5,161.5
C_3_GND_2270869 on TOP (solid shape): outline of 2370 points within 116.5,77.5 171.5,161.5
C_3_GND_2270869 on BOTTOM (solid shape): 127.95,96.45 127.95,85.75 126.81,84.61 126.64,84.58 126.55,84.72 126.55,85.05 126.29,85.05 126.15,85.14 126.18,85.31 126.54,86.4 125.92,87.38 125.85,87.51 125.92,87.64 126.55,88.78 125.92,89.92 125.85,90.05 125.92,90.18 126.55,91.32 125.92,92.46 125.85,92.59 125.92,92.72 126.55,93.89 125.88,95.03 125.8,95.16 125.88,95.29 126.49,96.2 126.19,97.25 126.16,97.41 126.3,97.5 126.9,97.5
C_3_GND_2270869 on BOTTOM (solid shape): outline of 1453 points within 116.5,77.5 171.5,161.5
C_3_GND_2270869 on IS1 (solid shape): outline of 2343 points within 116.5,77.5 171.5,161.5
C_3_GND_2270869 on IS2 (solid shape): outline of 2415 points within 116.5,77.5 171.5,161.5
C_4_GND_2270869 on TOP (solid shape): outline of 2370 points within 174.5,77.5 229.5,161.5
C_4_GND_2270869 on BOTTOM (solid shape): 185.95,96.45 185.95,85.75 184.81,84.61 184.64,84.58 184.55,84.72 184.55,85.05 184.29,85.05 184.15,85.14 184.18,85.31 184.54,86.4 183.92,87.38 183.85,87.51 183.92,87.64 184.55,88.78 183.92,89.92 183.85,90.05 183.92,90.18 184.55,91.32 183.92,92.46 183.85,92.59 183.92,92.72 184.55,93.89 183.88,95.03 183.8,95.16 183.88,95.29 184.49,96.2 184.19,97.25 184.16,97.41 184.3,97.5 184.9,97.5
C_4_GND_2270869 on BOTTOM (solid shape): outline of 1449 points within 174.5,77.5 229.5,161.5
C_4_GND_2270869 on IS1 (solid shape): outline of 2343 points within 174.5,77.5 229.5,161.5
C_4_GND_2270869 on IS2 (solid shape): outline of 2415 points within 174.5,77.5 229.5,161.5
C_5_GND_2270869 on TOP (solid shape): outline of 2370 points within 232.5,77.5 287.5,161.5
C_5_GND_2270869 on BOTTOM (solid shape): 243.95,96.45 243.95,85.75 242.81,84.61 242.64,84.58 242.55,84.72 242.55,85.05 242.29,85.05 242.15,85.14 242.18,85.31 242.54,86.4 241.92,87.38 241.85,87.51 241.92,87.64 242.55,88.78 241.92,89.92 241.85,90.05 241.92,90.18 242.55,91.32 241.92,92.46 241.85,92.59 241.92,92.72 242.55,93.89 241.88,95.03 241.8,95.16 241.88,95.29 242.49,96.2 242.19,97.25 242.16,97.41 242.3,97.5 242.9,97.5
C_5_GND_2270869 on BOTTOM (solid shape): outline of 1449 points within 232.5,77.5 287.5,161.5
C_5_GND_2270869 on IS1 (solid shape): outline of 2343 points within 232.5,77.5 287.5,161.5
C_5_GND_2270869 on IS2 (solid shape): outline of 2415 points within 232.5,77.5 287.5,161.5

Small or netless copper shapes (teardrops, artwork), in the pictures only: 15 on BOTTOM, 6 on IS1, 12 on IS2

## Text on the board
COMPVAL_TYPE_TOP: TITRE | TITLE | . | No EVOL | DESSINE/DRAWN | SR_ASCO | REV. | Nbr/Qty | DATE | 18-02-2015 | EVOLUTION/CHANGE | J.GESLIN | VERIFIE/CHECKED | NUMERO DOCUMENT/DOCUMENT NUMBER | DESS./DRAWN | APPROUVE/APPROVED | ..-..-.... | VERIF./CHECKED | PAGE | PN7120 NFC Controller Board-BeagleBone/Raspberry Pi Interface Board | 2 Esplanade Anton Philips | BP 2000 - COLOMBELLES | 14906 CAEN CEDEX 9 | SEMICONDUCTORS | OM5577 | / | 00
User.37: A
User.38: All rights are reserved. Reproduction in | whole or in part is prohibited without | the written consent of the copyright owner | Date : 18/02/2015 | Draw by : ASCO_SR | Checked by: J.GESLIN | Project : PN7120 | Material:FR4 TG150 LOW CTEz | Protection : SOLDERMASK | 16/10 17.5 uM of basic | Finition : NI/Au chemical | TOP BOTTOM | Marging : +/-0.1 | Manufact.level : 5 | Scale : 1/1 | Nbr of layers : 4 | Silkscreen | TOP   :YES | BOTTOM:NO | NXP Semiconductors | 2,Esplanade Anton Philips | Campus Effiscience Colombelles | BP 2000 - 14906 CAEN CEDEX 9 | Date | Draw by | Verify | Modifications | SIZE | REV. | IND. | PL. | BeagleBone/Raspberry Pi Interface Board | PN7120 NFC Controller Board | DRILL MANUFACTURING | H | G | F | E | D | C | B | A | 4 | 3 | 2 | 1 | A3 | OM5577-300 | 00
User.41: VIA1 | VIA2 | VIA1 : FLAT PAD VIA LASER TOP | LAYER 2 : WIRE =150u MINI | BGA 49 ball full 7x7 pitch 500u | (Filled Copper or resine) | PAD 200um, Drill 100um | DATE/CODE | 2/2 | SILKSCREEN
User.42: (BLANCHE) | CTE Z
User.45: OM5577 | . | 00 | 380 | FIGURE | DIAMETRE / HOLESIZE | 0,30 mm (PERCE) | 1,00 mm +0,10 -0,05 | 1,10 mm +0,10 -0,05 | 1,40 mm +0,10 -0,05 | 3,20 mm +0,15 -0,10 | 0,10 mm (LASER) | LEGENDE DE PERCAGE / DRILL LEGEND | ALL UNITS ARE IN MILLIMETERS | PLATED | Qte / Qty | 1264 | 678 | 48 | 272 | 20 | 198 | LAYER TOP IN2 | VIA 1 | 1 | 2 | NPC100 NICE DEMOBOARD V1.0 | A
